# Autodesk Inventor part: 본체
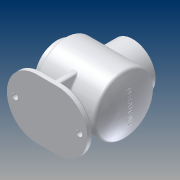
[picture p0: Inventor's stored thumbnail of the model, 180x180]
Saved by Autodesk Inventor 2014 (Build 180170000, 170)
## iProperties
Created: 2016-04
Part Number: 본체
Material: 알루미늄 6061
Document SubType Name: Modeling
Designer: owner
Density: 2.71 g/cm^3
Appearance: 알루미늄 - 평지
Mass: 909.943 g
Surface Area: 1236.82 cm^2
Volume: 335.772 cm^3
Author: owner
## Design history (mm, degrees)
sketch "스케치1"
  geometry: L1 (17.5, 0)-(-17.5, 0); L2 (17.5, 50)-(-17.5, 50); L3 (-17.5, -50)-(17.5, -50); A1 r 50 centre (17.5, 0) between (17.5, -50) and (17.5, 50); A2 r 50 centre (-17.5, 0) between (-17.5, 50) and (-17.5, -50); 2 further points
  constraints: 8 end point, 4 point on circle, 4 tangent, 2 centre point, 1 coincident, 1 horizontal, 1 midpoint, 1 parallel
  dimensions: "d0" = 100 distance between parallel lines of L2 L3; "d1" = 135 dimension on A1 A2
extrude "돌출1" new body sketch "스케치1" distance "d2" = 10; taper "d3" = 0 deg
sketch "스케치2"
  geometry: L1 (-17.5, -50)-(17.5, -50) reference; L2 (17.5, 50)-(-17.5, 50) reference; C1 r 5 at (-54, 0); C2 r 5 at (54, 0); 1 further point
  constraints: 2 centre point
  dimensions: "d4" = 10 diameter of C1; "d5" = 10 diameter of C2; "d6" = 54 distance of C2.centre point (0, 0); "d7" = 54 distance of point (0, 0) C1.centre; "d8" = 50 distance from line of L2 C1.centre; "d9" = 50 distance from line of L1 C2.centre
extrude "돌출2" cut sketch "스케치2" distance "d10" = 10; taper "d11" = 0 deg
sketch "스케치3"
  geometry: L1 (0, -50)-(0, 50) reference; C1 r 50 at (79, 0); 1 further point
  constraints: 1 centre point
  dimensions: "d12" = 79 distance from line of L1 C1.centre; "d14" = 100 diameter of C1; "d15" = 93.49332 distance of C1.centre L1.end
extrude "돌출3" join sketch "스케치3" stored distance "d16" = 100; taper "d17" = 0 deg
sketch "스케치5"
  geometry: L1 (50, 29)-(50, 129) reference; L2 (50, 129)-(50, 79); L3 (50, 79)-(60.913, 79); L4 (17.5, 0)-(-17.5, 0) reference; A1 r 120 centre (-59.087, 79) between (60.913, 79) and (50, 129); 1 further point
  constraints: 4 end point, 2 point on circle, 1 centre point, 1 perpendicular
  dimensions: "d18" = 120 radius of A1; "d19" = 79 distance between parallel lines of L4 L3; "d22" = 10.91288 distance from line of L3.end L1
revolve "회전1" sketch "스케치5" stored, may be unused: angle "d23" = 90 deg
sketch "스케치6"
  geometry: C1 r 50 at (0, 0) reference; C2 r 38 at (0, 0); 1 further point
  constraints: 1 centre point, 1 coincident
  dimensions: "d24" = 76 diameter of C2
extrude "돌출4" join sketch "스케치6" distance "d25" = 12; taper "d26" = 0 deg
hole "구멍1" diameter "d29" = 54; stored, may be unused: countersink angle "d33" = 90 deg, drill point angle "d35" = 0 deg; dims "d27" = 10, "d28" = 10, "d30" = 6, "d31" = 4, "d32" = 2, "d34" = 15
sketch "스케치7"
  geometry: L1 (-50, 129)-(50, 129) reference; L2 (-50, 29)-(50, 29) reference; L3 (48.058, 126)-(48.058, 79); L4 (48.058, 79)-(57.913, 79); A1 r 120 centre (-59.087, 79) between (50, 29) and (50, 129) reference; A2 r 117 centre (-59.087, 79) between (57.913, 79) and (48.058, 126); 1 further point
  constraints: 4 end point, 2 point on circle, 1 centre point, 1 parallel, 1 perpendicular
  dimensions: "d36" = 3 radial gap between concentric circles of A1 A2; "d39" = 50 distance between parallel lines of L1 L4; "d40" = 1.94236 distance from line of A1.end L3
revolve "회전2" sketch "스케치7" stored, may be unused: angle "d41" = 90 deg
hole "구멍2" diameter "d44" = 94; stored, may be unused: countersink angle "d48" = 90 deg, drill point angle "d50" = 0 deg; dims "d42" = 10, "d43" = 10, "d45" = 6, "d46" = 4, "d47" = 2, "d49" = 95.058
sketch "스케치9" dims "d51" = 65
  geometry: C1 r 27 at (0, 0) reference; C2 r 38 at (0, 0) reference; 3 further points
  constraints: 2 vertical alignment, 1 coincident, 2 other
hole "구멍3" sketch "스케치9" at (0, 32.5) diameter "d52" = 3.242; stored, may be unused: countersink angle "d56" = 90 deg, drill point angle "d58" = 118 deg; dims "d53" = 8, "d54" = 4, "d55" = 2, "d57" = 10
node "작업 평면1"
sketch "스케치10"
  geometry: C1 r 38 at (0, 0); 1 further point
  constraints: 1 centre point, 1 coincident
  dimensions: "d63" = 76 diameter of C1
extrude "돌출5" join sketch "스케치10" stored distance "d64" = 12; taper "d65" = 0 deg
sketch "스케치11" dims "d66" = 65
  geometry: C1 r 38 at (0, 0) reference; 2 further points
  constraints: 2 vertical alignment, 1 coincident, 2 other
hole "구멍4" sketch "스케치11" at (0, 32.5) diameter "d67" = 3.242; stored, may be unused: countersink angle "d71" = 90 deg, drill point angle "d73" = 118 deg; dims "d68" = 8, "d69" = 4, "d70" = 2, "d72" = 10
hole "구멍5" diameter "d79" = 54; stored, may be unused: countersink angle "d83" = 90 deg, drill point angle "d85" = 0 deg; dims "d77" = 10, "d78" = 10, "d80" = 8, "d81" = 4, "d82" = 2, "d84" = 44
sketch "스케치12"
  geometry: L1 (-17.5, 10)-(-67.5, 10) reference; L2 (67.5, 10)-(17.5, 10) reference; L3 (-40, 10)-(-36.487, 29.921); L4 (36.487, 29.921)-(40, 10); L5 (-40, 10)-(40, 10); L6 (-36.487, 29.921)-(36.487, 29.921); 1 further point
  constraints: 8 end point, 2 point on line, 1 parallel
  dimensions: "d86" = 40 horizontal distance of point (0, 0) L4.end; "d87" = 40 horizontal distance of L3.start point (0, 0); "d88" = 100 deg angle of L1 L3; "d89" = 100 deg angle of L2 L4; "d90" = 19.92068 distance between parallel lines of L6 L2
extrude "돌출6" join sketch "스케치12" stored distance "d91" = 10; taper "d92" = 0 deg
sketch "스케치13"
  geometry: L1 (10, -50)-(10, 50) reference; L2 (49, 40)-(10, 40); L3 (49, -40)-(10, -40); L4 (10, 40)-(10, -40); A1 r 50 centre (79, 0) between (49, 40) and (49, -40) reference; A2 r 50 centre (79, 0) between (49, 40) and (49, -40); 1 further point
  constraints: 6 end point, 4 point on circle, 3 perpendicular, 2 point on line, 1 centre point, 1 coincident, 1 concentric
  dimensions: "d93" = 40 distance from line of point (0, 0) L3; "d94" = 40 distance from line of L2 point (0, 0)
extrude "돌출7" join sketch "스케치13" stored distance "d95" = 10; taper "d96" = 0 deg
node "작업 평면4"
  node "작업 평면3"
fillet "모깎기2" dims "d103" = 5
fillet "모깎기3" dims "d104" = 2
fillet "모깎기4" dims "d105" = 2
chamfer "모따기1" distance "d106" = 3; stored, may be unused: second distance "d107" = 2, angle "d108" = 45 deg
chamfer "모따기2" distance "d109" = 1; stored, may be unused: second distance "d110" = 2, angle "d111" = 45 deg
fillet "모깎기5" dims "d112" = 3
fillet "모깎기6" dims "d113" = 3
fillet "모깎기7" dims "d114" = 3
fillet "모깎기8" dims "d115" = 3
fillet "모깎기9" dims "d116" = 3
fillet "모깎기10" dims "d117" = 3
fillet "모깎기11" dims "d118" = 3
fillet "모깎기12" dims "d119" = 3
chamfer "모따기3" distance "d120" = 1; stored, may be unused: second distance "d121" = 2, angle "d122" = 45 deg
node "작업 평면5"
sketch "스케치18"
  geometry: L1 (0, -50)-(0, 50) reference; L2 (48.016, 40)-(13, 40) reference; 2 further points
  constraints: 1 other
  dimensions: "d124" = 79 distance from line of L1 point (79, 0); "d125" = 40 distance from line of L2 point (79, 0)
feature "엠보싱1" sketch "스케치18" dims "d126" = 0.5, "d127" = 0
fillet "모깎기13" dims "d128" = 5
node "솔리드1"
pattern_circular "원형 패턴1" dims angle "d60" = 360 deg
pattern_circular "원형 패턴2" dims angle "d75" = 360 deg
other parameters: "d62" = -144, "d99" = 0.5, "d123" = 92.5
